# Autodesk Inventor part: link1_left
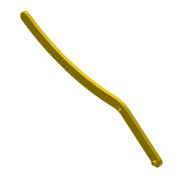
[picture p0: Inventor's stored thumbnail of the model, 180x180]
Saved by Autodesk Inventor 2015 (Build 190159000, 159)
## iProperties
Created: 2020-09
Part Number: link1_left
Material: 一般
Document SubType Name: Modeling
Designer: 徐冠倫
Mass: 167.388 g
Surface Area: 456.359 cm^2
Volume: 167.388 cm^3
Density: 1 g/cm^3
Appearance: 預設
Author: 徐冠倫
Author: IANNIAN
Title: D:\Desktop\OCW-Computer-Aided Engineering Drawing\OCW_Topic 06：組合圖與機構模擬(進階)\6-1_Flexibility\Mechanical Gripper(piston)\Mechanical Gripper(STP)\link1_left.stp
Creation Date: 2020-09-04
Sending System: Autodesk Inventor 2020
Preprocessor: ST-DEVELOPER v18
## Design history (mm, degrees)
node "link1_left1"
body "Solid1"
node "Base1"
